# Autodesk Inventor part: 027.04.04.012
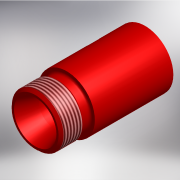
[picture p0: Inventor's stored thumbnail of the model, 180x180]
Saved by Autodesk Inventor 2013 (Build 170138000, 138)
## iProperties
Shininess: 20.0
Length Units: 11269
Angle Units: 11279
Time Units: 11290
Mass Units: 11283
Length Display Precision: 3
Angle Display Precision: 2
Created: 2001-08
Part Number: 027.04.04.012
Material: Steel, Mild
Document SubType Name: Modeling
Designer: SOleg
Density: 7.86 g/cm^3
Density: 0.0
Volumn: 0.0
Area: 0.0
PropertySet Name: Model Information
Control State: 0
Master: False
Checked Out: True
Checked Out Date: 2008-10-15
Last Check In Date: 2008-10-15
Author: SOleg
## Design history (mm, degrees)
node "WorkAxis1"
node "RevolutionFull1" dims "d4" = 360 deg
  sketch "Sketch2"
    geometry: L1 (0, 15)-(0, -35); L2 (18, 15)-(0, 15); L3 (18, -35)-(18, 15); L4 (0, -35)-(18, -35); L5 (0, 15)-(0, -35)
    constraints: 10 end point, 2 horizontal, 2 vertical, 1 other
    dimensions: "d1" = 50 distance of L3.start L2.start; "d3" = 36 diameter of L3.start L1
node "WorkPlane2"
node "WorkPlane3"
node "WorkPlane4"
node "RevolutionFull2" dims "d18" = 360 deg
node "WorkPoint2"
node "WorkPlane1"
node "RevolutionFull3" dims "d24" = 360 deg
node "Sketch7"
node "ExtrusionBlind1" dims "d39" = 5, "d40" = 0
body "Solid1"
sketch "Sketch1"
  geometry: L1 (0, -35)-(0, 15)
  constraints: 2 end point
sketch "Sketch4"
  geometry: 1 further point
node "Hole1" dims "d25" = 19, "d26" = 27, "d27" = 2, "d28" = 37 deg, "d29" = 60, "d30" = 120 deg
node "Hole2" dims "d31" = 19, "d32" = 4, "d33" = 2, "d34" = 60 deg, "d35" = 19, "d36" = 120 deg
thread "Thread1" dims "d41" = 10, "d42" = 0
sketch "Sketch3"
  geometry: L1 (0, 35)-(0, 15); L2 (14.9, 35)-(0, 35); L3 (16.5, 33.4)-(14.9, 35); L4 (16.5, 15)-(16.5, 33.4); L5 (0, 15)-(16.5, 15); L6 (0, 35)-(0, 15); C1 r 18 at (0, 15)
  constraints: 12 end point, 2 horizontal, 2 vertical, 1 centre point, 1 coincident
  dimensions: "d11" = 45 deg angle of L4 L3; "d13" = 1.6 horizontal distance of L2.start L3.start; "d15" = 20 vertical distance of L4.start L2.start; "d17" = 33 diameter of L4.start L1
sketch "Sketch5"
  geometry: L1 (15, 19.793)-(15, 16.5); L2 (16.5, 21.5)-(15.146, 20.146); L3 (16.5, 15)-(16.5, 21.5); L4 (16.5, 15)-(15, 15); L5 (15, 15)-(15, 16.5); L6 (16.5, 24.2)-(16.5, 25.2); L7 (9, 15)-(10, 15); L8 (0, 43.278)-(0, -43.278); A1 r 1.5 centre (16.5, 16.5) between (15, 16.5) and (16.5, 15); A2 r 0.5 centre (15.5, 19.793) between (15.146, 20.146) and (15, 19.793)
  constraints: 16 end point, 4 point on circle, 4 tangent, 3 vertical, 2 centre point, 2 collinear, 1 horizontal
  dimensions: "d21" = 1.5 distance of L3.start L4.end; "d23" = 6.5 distance of L3.start L2.start
sketch "Sketch6"
  geometry: C1 r 14.9 at (0, 0) reference; 1 further point
sketch "Sketch8"
  geometry: C1 r 13 at (0, -5)
  constraints: 1 centre point
  dimensions: "d38" = 26 diameter of C1
other parameters: "d2" = 36 (derived), "d5" = 0, "d6" = 0, "d7" = 0, "d8" = 0, "d9" = 0, "d10" = 45 deg (derived), "d12" = 1.6 (derived), "d16" = 33 (derived), "d19" = 0, "d20" = 1.5 (derived), "d22" = 6.5 (derived), "d37" = 26 (derived)
